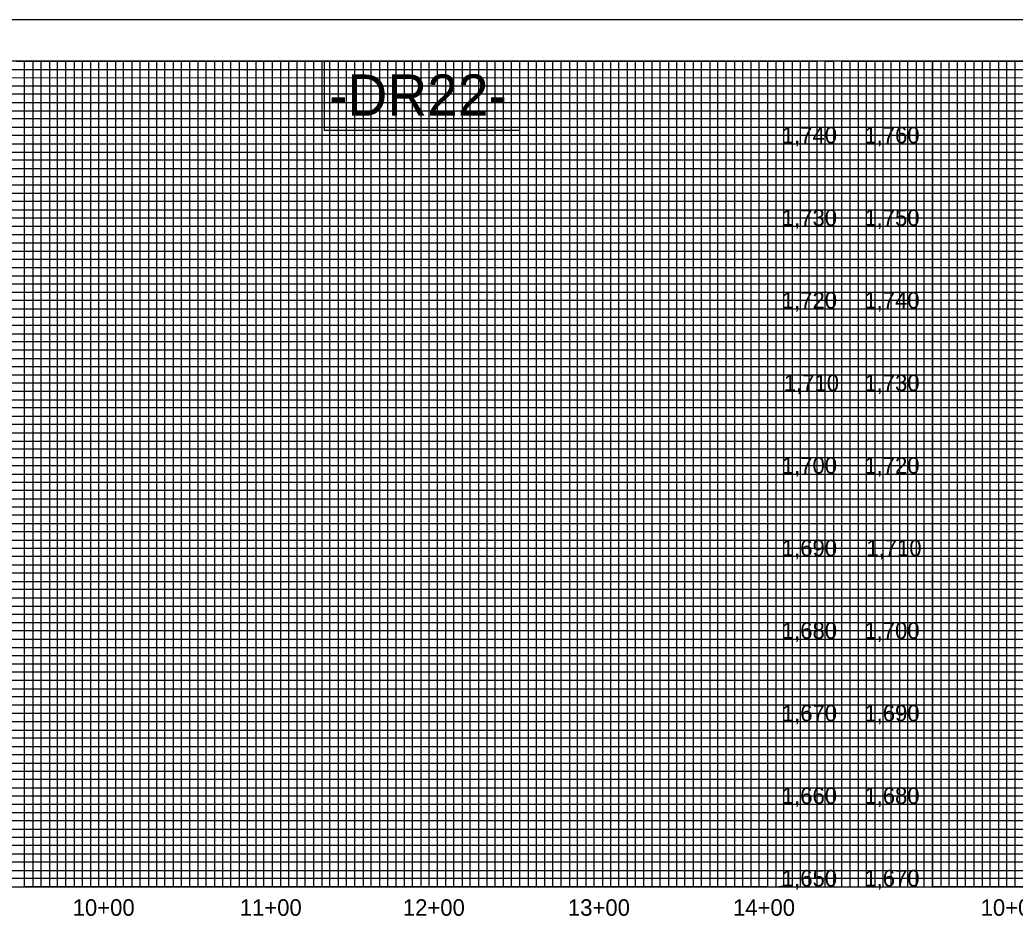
# Model space of a CAD drawing. Extents: x 505602 to 527661, y 418813 to 494436.
# Drawn here: x 506166 to 506769, y 483662 to 484209 of the extents above; entities that cross this region are included whole.
import ezdxf

# ---------------------------------------------------------------- set-up
doc = ezdxf.new("R2010")
doc.units = 0
for name, color, linetype in [('Exist Vertical Profile Vertical Axis Label', 7, 'Continuous'), ('Old_Level_1', 7, 'Continuous'), ('Prop Grid Mask', 7, 'Continuous'), ('Sheet Layout Profile Border Port 2', 7, 'Continuous'), ('Sheet Plot Border Outside CELL', 7, 'Continuous'), ('Sheet Profile CELL', 7, 'Continuous'), ('Sheet Profile Grid Major CELL', 7, 'Continuous'), ('Sheet Profile Grid Middle CELL', 7, 'Continuous'), ('Sheet Profile Grid Minor CELL', 7, 'Continuous')]:
    doc.layers.add(name, color=color, linetype=linetype)

msp = doc.modelspace()

# ---------------------------------------------------------------- linework, layer by layer
at = {"layer": 'Prop Grid Mask'}
msp.add_lwpolyline([(506469.08, 484183.71), (506350.61, 484183.71), (506350.61, 484142), (506469.08, 484142)], close=True, dxfattribs=at)
at = {"layer": 'Sheet Layout Profile Border Port 2'}
for points in [[(506169.08, 484183.71), (506619.08, 484183.71), (506619.08, 483683.71), (506169.08, 483683.71)], [(506719.08, 484183.71), (507069.08, 484183.71), (507069.08, 483683.71), (506719.08, 483683.71)]]:
    msp.add_lwpolyline(points, close=True, dxfattribs=at)
at = {"layer": 'Sheet Plot Border Outside CELL'}
msp.add_lwpolyline([(505602.08, 483108.71), (507286.08, 483108.71), (507286.08, 484208.71), (505602.08, 484208.71)], close=True, dxfattribs=at)
at = {"layer": 'Sheet Profile CELL'}
for p, q in [((506669.08, 483683.71), (506669.08, 484183.71)), ((505769.08, 483683.71), (507269.08, 483683.71))]:
    msp.add_line(p, q, dxfattribs=at)
msp.add_lwpolyline([(507269.08, 484183.71), (505769.08, 484183.71), (505769.08, 483133.71), (507269.08, 483133.71)], close=True, dxfattribs=at)
at = {"layer": 'Sheet Profile Grid Major CELL'}
for points in [[(506119.08, 483683.71), (506169.08, 483683.71), (506169.08, 484183.71), (506219.08, 484183.71), (506219.08, 483683.71), (506269.08, 483683.71), (506269.08, 484183.71), (506319.08, 484183.71), (506319.08, 483683.71), (506369.08, 483683.71), (506369.08, 484183.71), (506419.08, 484183.71), (506419.08, 483683.71), (506469.08, 483683.71), (506469.08, 484183.71), (506519.08, 484183.71), (506519.08, 483683.71), (506569.08, 483683.71), (506569.08, 484183.71), (506619.08, 484183.71), (506619.08, 483683.71), (506669.08, 483683.71), (506669.08, 484183.71), (506719.08, 484183.71), (506719.08, 483683.71), (506769.08, 483683.71), (506769.08, 484183.71), (506819.08, 484183.71)], [(505769.08, 484133.71), (507069.08, 484133.71)], [(507069.08, 484083.71), (505769.08, 484083.71), (505769.08, 484033.71), (507069.08, 484033.71)], [(507269.08, 483983.71), (505769.08, 483983.71), (505769.08, 483933.71), (507269.08, 483933.71)], [(507269.08, 483883.71), (505769.08, 483883.71), (505769.08, 483833.71), (507269.08, 483833.71)], [(507269.08, 483783.71), (505769.08, 483783.71), (505769.08, 483783.71), (505769.08, 483733.71), (507269.08, 483733.71)]]:
    msp.add_lwpolyline(points, dxfattribs=at)
at = {"layer": 'Sheet Profile Grid Middle CELL'}
msp.add_line((505769.08, 484158.71), (507069.03, 484158.71), dxfattribs=at)
msp.add_line((505769.08, 484158.71), (507069.03, 484158.71), dxfattribs=at)
for points in [[(506144.08, 483683.71), (506194.08, 483683.71), (506194.08, 484183.71), (506244.08, 484183.71), (506244.08, 483683.71), (506294.08, 483683.71), (506294.08, 484183.71), (506344.08, 484183.71), (506344.08, 483683.71), (506394.08, 483683.71), (506394.08, 483683.71), (506394.08, 484183.71), (506444.08, 484183.71), (506444.08, 483683.71), (506494.08, 483683.71), (506494.08, 484183.71), (506544.08, 484183.71), (506544.08, 483683.71), (506594.08, 483683.71), (506594.08, 484183.71), (506644.08, 484183.71), (506644.08, 483683.71), (506694.08, 483683.71), (506694.08, 484183.71), (506744.08, 484183.71), (506744.08, 483683.71), (506794.08, 483683.71)], [(507069.08, 484108.71), (505769.08, 484108.71), (505769.08, 484058.71), (507069.08, 484058.71)], [(507269.08, 484008.71), (505769.08, 484008.71), (505769.08, 483958.71), (507094.08, 483958.71)], [(507269.08, 483908.71), (505769.08, 483908.71), (505769.08, 483858.71), (507269.08, 483858.71)], [(507269.08, 483808.71), (505769.08, 483808.71), (505769.08, 483758.71), (507269.08, 483758.71)], [(507269.08, 483708.71), (505769.08, 483708.71)]]:
    msp.add_lwpolyline(points, dxfattribs=at)
at = {"layer": 'Sheet Profile Grid Minor CELL'}
for p, q in [((505819.08, 484178.71), (507069.08, 484178.71)), ((507069.08, 484173.71), (505819.08, 484173.36)), ((505819.08, 484168.71), (507069.08, 484168.71)), ((507069.03, 484048.71), (505819.08, 484048.71)), ((507069.08, 484043.71), (505819.08, 484043.71)), ((507069.08, 484038.71), (505819.08, 484038.71)), ((505819.08, 484028.71), (507069.08, 484028.71)), ((507069.08, 484023.71), (505819.08, 484023.71)), ((505819.08, 484018.71), (507219.08, 484018.71)), ((507219.08, 483998.71), (505819.08, 483998.71)), ((505819.08, 483993.71), (507219.08, 483993.71)), ((507219.08, 483973.71), (505819.08, 483973.71)), ((505819.08, 483968.71), (507219.08, 483968.71)), ((507219.08, 483948.71), (505819.08, 483948.71)), ((505819.08, 483943.71), (507219.08, 483943.71)), ((507219.08, 483938.71), (505819.08, 483938.71)), ((505819.08, 483928.71), (507219.08, 483928.71)), ((507219.08, 483923.71), (505819.08, 483923.71)), ((505819.08, 483918.71), (507219.08, 483918.71)), ((507219.08, 483913.71), (505819.08, 483913.71)), ((505819.08, 483903.71), (507219.08, 483903.71)), ((507219.08, 483898.71), (505819.08, 483898.71)), ((505819.08, 483893.71), (507219.08, 483893.71)), ((507219.08, 483888.71), (505819.08, 483888.71)), ((505819.08, 483878.71), (507219.08, 483878.71)), ((507219.08, 483873.71), (505819.08, 483873.71)), ((505819.08, 483868.71), (507219.08, 483868.71)), ((507219.08, 483863.71), (505819.08, 483863.71)), ((505819.08, 483853.71), (507219.08, 483853.71)), ((507219.08, 483848.71), (505819.08, 483848.71)), ((505819.08, 483843.71), (507219.08, 483843.71)), ((507219.08, 483838.71), (505819.08, 483838.71)), ((505819.08, 483828.71), (507219.08, 483828.71)), ((507219.08, 483823.71), (505819.08, 483823.71)), ((505819.08, 483818.71), (507219.08, 483818.71)), ((507219.08, 483813.71), (505819.08, 483813.71)), ((505819.08, 483803.71), (507219.08, 483803.71)), ((507219.08, 483798.71), (505819.08, 483798.71)), ((507219.08, 483793.71), (505819.08, 483793.71)), ((507219.08, 483788.71), (505819.08, 483788.71)), ((505819.08, 483778.71), (507219.08, 483778.71)), ((507219.08, 483773.71), (505819.08, 483773.71)), ((505819.08, 483768.71), (507219.08, 483768.71)), ((507219.08, 483763.71), (505819.08, 483763.71)), ((505819.08, 483753.71), (507219.08, 483753.71)), ((507219.08, 483748.71), (505819.08, 483748.71)), ((505819.08, 483743.71), (507219.08, 483743.71)), ((507219.08, 483738.71), (505819.08, 483738.71)), ((505819.08, 483728.71), (507219.08, 483728.71)), ((507219.08, 483723.71), (505819.08, 483723.71)), ((505819.08, 483718.71), (507219.08, 483718.71)), ((507219.08, 483713.71), (505819.08, 483713.71)), ((505819.08, 483703.71), (507219.08, 483703.71)), ((507219.08, 483698.71), (505819.08, 483698.71)), ((505819.08, 483693.71), (507219.08, 483693.71))]:
    msp.add_line(p, q, dxfattribs=at)
for points in [[(506164.08, 484183.71), (506174.08, 484183.71), (506174.08, 483683.71), (506179.08, 483683.71), (506179.08, 484183.71), (506184.08, 484183.71), (506184.08, 483683.71), (506189.08, 483683.71), (506189.08, 484183.71), (506199.08, 484183.71), (506199.08, 483683.71), (506204.08, 483683.71), (506204.08, 484183.71), (506209.08, 484183.71), (506209.08, 483683.71), (506214.08, 483683.71), (506214.08, 484183.71), (506224.08, 484183.71), (506224.08, 483683.71), (506229.08, 483683.71), (506229.08, 484183.71), (506234.08, 484183.71), (506234.08, 483683.71), (506239.08, 483683.71), (506239.08, 484183.71), (506249.08, 484183.71), (506249.08, 483683.71), (506254.08, 483683.71), (506254.08, 484183.71), (506259.08, 484183.71), (506259.08, 483683.71), (506264.08, 483683.71), (506264.08, 484183.71), (506274.08, 484183.71), (506274.08, 483683.71), (506279.08, 483683.71), (506279.08, 484183.71), (506284.08, 484183.71), (506284.08, 483683.71), (506289.08, 483683.71), (506289.08, 484183.71), (506299.08, 484183.71), (506299.08, 483683.71), (506304.08, 483683.71), (506304.08, 484183.71), (506309.08, 484183.71), (506309.08, 483683.71), (506314.08, 483683.71), (506314.08, 484183.71), (506324.08, 484183.71), (506324.08, 483683.71), (506329.08, 483683.71), (506329.08, 484183.71), (506334.08, 484183.71), (506334.08, 483683.71), (506339.08, 483683.71), (506339.08, 484183.71), (506349.08, 484183.71)], [(506349.08, 484183.71), (506349.08, 483683.71), (506354.08, 483683.71), (506354.08, 484183.71), (506359.08, 484183.71), (506359.08, 483683.71), (506364.08, 483683.71), (506364.08, 484183.71), (506374.08, 484183.71), (506374.08, 483683.71), (506379.08, 483683.71), (506379.08, 484183.71), (506384.08, 484183.71), (506384.08, 483683.71), (506389.08, 483683.71), (506389.08, 484183.71), (506399.08, 484183.71), (506399.08, 483683.71), (506404.08, 483683.71), (506404.08, 484183.71), (506409.08, 484183.71), (506409.08, 483683.71), (506414.08, 483683.71), (506414.08, 484183.71), (506424.08, 484183.71), (506424.08, 483683.71), (506429.08, 483683.71), (506429.08, 484183.71), (506434.08, 484183.71), (506434.08, 483683.71), (506439.08, 483683.71), (506439.08, 484183.71), (506449.08, 484183.71), (506449.08, 483683.71), (506454.08, 483683.71), (506454.08, 484183.71), (506459.08, 484183.71), (506459.08, 483683.71), (506464.08, 483683.71), (506464.08, 484183.71), (506474.08, 484183.71), (506474.08, 483683.71), (506474.08, 483683.71), (506479.08, 483683.71), (506479.08, 484183.71), (506484.08, 484183.71), (506484.08, 483683.71), (506489.08, 483683.71), (506489.08, 484183.71), (506499.08, 484183.71), (506499.08, 483683.71), (506504.08, 483683.71), (506504.08, 484183.71), (506509.08, 484183.71), (506509.08, 483683.71), (506514.08, 483683.71), (506514.08, 484183.71), (506524.08, 484183.71), (506524.08, 483683.71), (506529.08, 483683.71), (506529.08, 484183.71), (506534.08, 484183.71), (506534.08, 483683.71), (506539.08, 483683.71), (506539.08, 484183.71), (506549.08, 484183.71), (506549.08, 483683.71), (506554.08, 483683.71), (506554.08, 484183.71), (506559.08, 484183.71), (506559.08, 483683.71), (506564.08, 483683.71), (506564.08, 484183.71), (506574.08, 484183.71), (506574.08, 483683.71), (506579.08, 483683.71), (506579.08, 484183.71), (506584.08, 484183.71), (506584.08, 483683.71), (506589.08, 483683.71), (506589.08, 484183.71), (506599.08, 484183.71), (506599.08, 483683.71), (506604.08, 483683.71), (506604.08, 484183.71), (506609.08, 484183.71), (506609.08, 483683.71), (506614.08, 483683.71), (506614.08, 484183.71), (506624.08, 484183.71), (506624.08, 483683.71), (506628.78, 483684.26), (506629.08, 483683.71), (506629.08, 484183.71), (506634.08, 484183.71), (506634.08, 483683.71), (506639.08, 483683.71), (506639.08, 484183.71), (506649.08, 484183.71), (506649.08, 483683.71), (506654.08, 483683.71)], [(506654.08, 483683.71), (506654.08, 484183.71), (506659.08, 484183.71), (506659.08, 483683.71), (506664.08, 483683.71), (506664.08, 484183.71), (506674.08, 484183.71), (506674.08, 483683.71), (506679.08, 483683.71), (506679.08, 484183.71), (506684.08, 484183.71), (506684.08, 483683.71), (506689.08, 483683.71), (506689.08, 484183.71), (506699.08, 484183.71), (506699.08, 483683.71), (506704.08, 483683.71), (506704.08, 484183.71), (506709.08, 484183.71), (506709.08, 483683.71), (506714.08, 483683.71), (506714.08, 484183.71), (506724.08, 484183.71), (506724.08, 483683.71), (506729.08, 483683.71), (506729.08, 484183.71), (506734.08, 484183.71), (506734.08, 483683.71), (506739.08, 483683.71), (506739.08, 484183.71), (506749.08, 484183.71), (506749.08, 483683.71), (506754.08, 483683.71), (506754.08, 484183.71), (506759.08, 484183.71), (506759.08, 483683.71), (506764.08, 483683.71), (506764.08, 484183.71), (506774.08, 484183.71)], [(507069.08, 484163.71), (505819.08, 484163.71), (505819.08, 484153.71), (507069.08, 484153.71)], [(507069.03, 484148.71), (505819.08, 484148.71), (505819.08, 484143.71), (507069.08, 484143.71)], [(507069.08, 484138.71), (505819.08, 484138.71), (505819.08, 484128.71), (507069.08, 484128.71)], [(507069.08, 484123.71), (505819.08, 484123.71), (505819.08, 484118.71), (507069.08, 484118.71)], [(507069.08, 484113.71), (505819.08, 484113.71), (505819.08, 484103.71), (507069.08, 484103.71)], [(507069.08, 484098.71), (505819.08, 484098.71), (505819.08, 484093.71), (507069.08, 484093.71)], [(507069.08, 484088.71), (505819.08, 484088.71), (505819.08, 484078.71), (507069.08, 484078.71)], [(507069.08, 484073.61), (505819.18, 484073.61), (505819.18, 484068.71), (507069.08, 484068.71)], [(507069.08, 484063.71), (505819.08, 484063.71), (505819.08, 484053.71), (507069.08, 484053.71)], [(507219.08, 484013.71), (505819.08, 484013.71), (505819.08, 484003.71), (507219.08, 484003.71)], [(507219.08, 483988.71), (505819.08, 483988.71), (505819.08, 483978.71), (507219.08, 483978.71)], [(507219.08, 483963.71), (505819.08, 483963.71), (505819.08, 483953.71), (507219.08, 483953.71)], [(507219.08, 483688.71), (505819.08, 483688.71)]]:
    msp.add_lwpolyline(points, dxfattribs=at)

# ---------------------------------------------------------------- texts
at = {"layer": 'Exist Vertical Profile Vertical Axis Label'}
for s, p in [('1,740', (506627.78, 484133.96)), ('1,760', (506677.78, 484133.96)), ('1,730', (506627.78, 484083.96)), ('1,750', (506677.78, 484083.96)), ('1,720', (506627.78, 484033.96)), ('1,740', (506677.78, 484033.96)), ('1,710', (506628.97, 483983.96)), ('1,730', (506677.78, 483983.96)), ('1,700', (506627.78, 483933.96)), ('1,720', (506677.78, 483933.96)), ('1,690', (506627.78, 483883.96)), ('1,710', (506678.97, 483883.96)), ('1,680', (506627.78, 483833.96)), ('1,700', (506677.78, 483833.96)), ('1,670', (506627.78, 483783.96)), ('1,690', (506677.78, 483783.96)), ('1,660', (506627.78, 483733.96)), ('1,680', (506677.78, 483733.96)), ('1,650', (506627.78, 483683.96)), ('1,670', (506677.78, 483683.96)), ('10+00', (506198.21, 483666.21)), ('11+00', (506299.41, 483666.21)), ('12+00', (506398.21, 483666.21)), ('13+00', (506498.21, 483666.21)), ('14+00', (506598.21, 483666.21)), ('10+00', (506748.21, 483666.21))]:
    msp.add_text(s, height=10, dxfattribs=at).set_placement(p)
at = {"layer": 'Old_Level_1'}
msp.add_text('-DR22-', height=25, dxfattribs=at).set_placement((506353.53, 484150.68))

doc.saveas('drawing.dxf')
